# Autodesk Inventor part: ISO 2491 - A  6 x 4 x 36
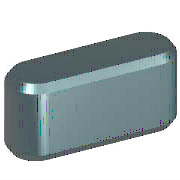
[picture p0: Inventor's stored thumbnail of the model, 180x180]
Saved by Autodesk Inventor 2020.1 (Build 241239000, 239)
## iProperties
Created: 2019-01
Part Number: ISO 2491 - A  6 x 4 x 36
Material: Stahl, weich
Description: Passfedern
Document SubType Name: Modeling
Standard: ISO 2491
Designer: lutzd
Standard Revision: First edition 1974-08-15
Standards Organization: ISO
Language: de-DE
Size Designation: A  6 x 4 x 36
Categories: <MemberInstance><Categories><Category DisplayName="Wellenteile" InternalName="7f7aeb1f-a693-4053-b835-cee3144e0d98" Mnemonic="SHFT"><Category DisplayName="Passf
Mass: 6.44183 g
Surface Area: 6.94579 cm^2
Volume: 0.820615 cm^3
Density: 7.85 g/cm^3
Appearance: Halbpoliert
IsCustomPart: 0
Author: lutzd
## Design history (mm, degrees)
workplane "Work Plane1"
workplane "Work Plane2"
sketch "Skizze1"
  geometry: L1 (3, 3)-(33, 3); L2 (33, -3)-(3, -3); L3 (0, 9.4)-(0, -7.4) reference; L4 (-5, 0)-(30, 0) reference; L5 (36, 0)-(36, 7); A1 r 3 centre (3, 0) between (3, 3) and (3, -3); A2 r 3 centre (33, 0) between (33, -3) and (33, 3)
  constraints: 6 end point, 5 point on circle, 4 tangent, 3 point on line, 2 centre point, 1 horizontal, 1 parallel, 1 perpendicular
  dimensions: "d0" = 3 radius of A1 (= 0.5 x PB); "d13" = 3 radius of A2 (= 0.5 x PB); "d14" = 36 distance between parallel lines of L5 L3 (= NLG)
extrude "Körper1" new body sketch "Skizze1" taper "d3" = 0 deg; stored distance "d4" = 10
workplane "Work Plane3"
body "Solid1"
chamfer "Fase1" distance "d8" = 0.4 (= PHH); stored, may be unused: second distance "d9" = 0.4 (= PHH), angle "d15" = 45 deg
other parameters: "d1" = -2.5 (= -PNT), "d2" = 1.5 (= PH - PNT), "NLG" = 36 [user parameter; used in 1 equation term], "PB" = 6 [user parameter; used in 2 equation terms], "PNT" = 2.5 [user parameter; used in 2 equation terms], "PH" = 4 [user parameter; used in 1 equation term], "PHH" = 0.4 [user parameter; used in 2 equation terms], "d10" = 0, "d16" = 0, "d17" = 0, "d18" = 0, "RR" = 0.16 [user parameter], "WDMIN" = 17 [user parameter], "WDMAX" = 22 [user parameter], "PLB1" = 36 [user parameter], "PLB2" = 36 [user parameter], "PUEB" = 1.8 [user parameter]
